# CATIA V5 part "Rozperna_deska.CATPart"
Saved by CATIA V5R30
Part number: Rozperna_deska
Definition: F 70_346446_62_96_1730
Nomenclature: F 70_346446_62_96_1730
Source: Unknown
Description: PART--DESC
Bounding box of the stored display mesh (mm): x -223 to 223, y -173 to 173, z -224 to -128
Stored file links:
  E:\Bakalarka\Model\Forma_v7\Rozperna_deska.CATPart
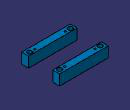
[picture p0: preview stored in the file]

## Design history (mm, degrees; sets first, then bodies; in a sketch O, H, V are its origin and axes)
Body1 "MANIFOLD_SOLID_BREP #4106" (main body)
  Solid1: solid without history
  DatumCurve1 to DatumCurve8
  DatumSurface1
  DatumCurve9 to DatumCurve16
  Sketch1 on face of DatumSurface1, origin (0, 0, -92), H (1, 0, 0), V (0, -1, 0)
Body2 "MANIFOLD_SOLID_BREP #4107"
  DatumSurface2
  Solid2: solid without history
  DatumCurve17
  DatumCurve18
  Sketch2 on face of DatumSurface2, origin (223, 0, 0), H (0, -1, 0), V (0, 0, 1)
    reference projected arc E2 centre (0, -58) radius 15 from (15, -58) to (-15, -58) ccw from edge of DatumCurve18
    point P5 (0, -58)
    concentricity: P5 E2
